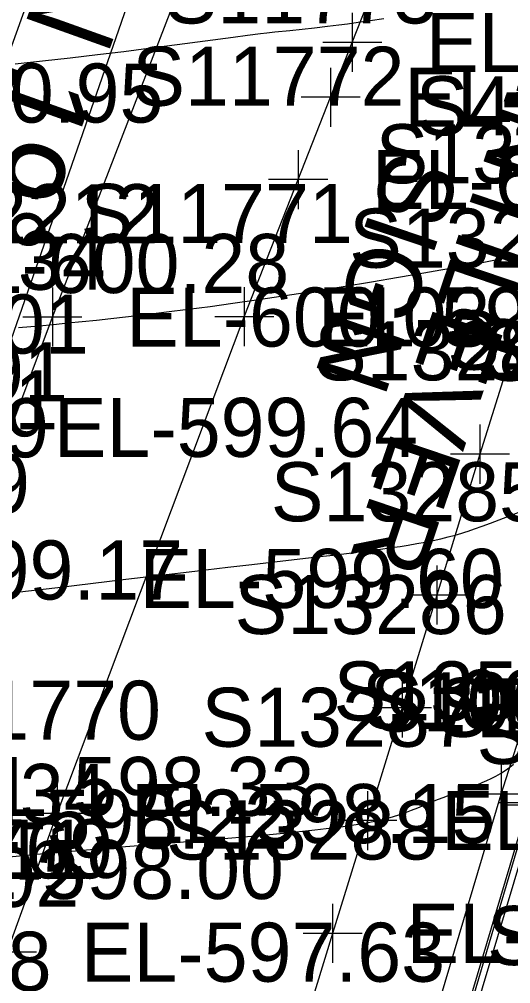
# Model space of a CAD drawing. Extents: x 1729869 to 1735532, y 648588 to 653771.
# Drawn here: x 1730424.1 to 1730457.4, y 652724.8 to 652790.1 of the extents above; entities that cross this region are included whole.
import ezdxf

# ---------------------------------------------------------------- set-up
doc = ezdxf.new("R2010")
doc.units = 0
for name, color, linetype in [('SURVEY - CENTERLINE - Preliminary', 7, 'Continuous'), ('SURVEY - CENTERLINE - Preliminary Text', 7, 'Continuous'), ('SURVEY - CONTOURS - Index with Text', 7, 'Continuous'), ('SURVEY - CONTOURS - Intermediate with optional Text', 7, 'Continuous'), ('SURVEY - DRAINAGE - Storm Sewer', 7, 'Continuous'), ('SURVEY - DRAINAGE - Storm Sewer - Points - Numbers', 7, 'Continuous'), ('SURVEY - DTM - Breaklines', 7, 'Continuous'), ('SURVEY - DTM - Breaklines - Points - Locators', 7, 'Continuous'), ('SURVEY - DTM - Breaklines - Points - Numbers', 7, 'Continuous'), ('SURVEY - ROADSIDE BARRIERS - Points - Numbers', 7, 'Continuous'), ('SURVEY - TRAFFIC CONTROL - Pavement Marking - Points - Elevations', 7, 'Continuous'), ('SURVEY - TRAFFIC CONTROL - Pavement Marking - Points - Locators', 7, 'Continuous'), ('SURVEY - TRAFFIC CONTROL - Pavement Marking - Points - Numbers', 7, 'Continuous'), ('SURVEY - TRAFFIC CONTROL - Pavement Marking with Text', 7, 'Continuous'), ('SURVEY - TRAFFIC CONTROL - Signs - Points - Elevations', 7, 'Continuous'), ('SURVEY - TRAFFIC CONTROL - Signs and Devices with Text', 7, 'Continuous'), ('SURVEY - TRANSPORTATION - Features', 7, 'Continuous'), ('SURVEY - TRANSPORTATION - Features - Points - Locators', 7, 'Continuous'), ('SURVEY - TRANSPORTATION - Features - Points - Numbers', 7, 'Continuous'), ('SURVEY - TRANSPORTATION - Roads', 7, 'Continuous'), ('SURVEY - TRANSPORTATION - Roads - Points - Elevations', 7, 'Continuous'), ('SURVEY - TRANSPORTATION - Roads - Points - Locators', 7, 'Continuous'), ('SURVEY - TRANSPORTATION - Roads - Points - Numbers', 7, 'Continuous')]:
    doc.layers.add(name, color=color, linetype=linetype)

msp = doc.modelspace()

# ---------------------------------------------------------------- linework, layer by layer
at = {"layer": 'SURVEY - CENTERLINE - Preliminary'}
msp.add_line((1730367.125, 652630.456), (1730449.207, 652859.92), dxfattribs=at)
at = {"layer": 'SURVEY - CONTOURS - Index with Text'}
msp.add_lwpolyline([(1730424.074, 652769.267), (1730425.459, 652769.388), (1730426.443, 652769.479), (1730427.415, 652769.573), (1730428.382, 652769.67), (1730429.351, 652769.772), (1730430.331, 652769.878), (1730431.328, 652769.99), (1730432.694, 652770.149), (1730434.105, 652770.319), (1730435.56, 652770.502), (1730437.059, 652770.698), (1730438.603, 652770.91), (1730440.19, 652771.137), (1730442.134, 652771.429), (1730444.106, 652771.738), (1730446.068, 652772.054), (1730447.985, 652772.372), (1730449.823, 652772.682), (1730451.545, 652772.978), (1730452.683, 652773.176), (1730453.752, 652773.364), (1730454.759, 652773.546), (1730455.711, 652773.723), (1730456.615, 652773.897), (1730457.478, 652774.071)], dxfattribs=at)
at = {"layer": 'SURVEY - CONTOURS - Intermediate with optional Text'}
for points in [[(1730423.842, 652787.131), (1730425.703, 652787.324), (1730427.575, 652787.532), (1730429.42, 652787.749), (1730431.202, 652787.968), (1730432.885, 652788.181), (1730434.827, 652788.435), (1730438.625, 652788.939), (1730439.579, 652789.063), (1730440.471, 652789.173), (1730440.899, 652789.224), (1730441.429, 652789.285), (1730442.448, 652789.396), (1730444.123, 652789.574), (1730445.014, 652789.676), (1730445.783, 652789.77), (1730446.368, 652789.846), (1730447.092, 652789.945), (1730447.908, 652790.062), (1730448.83, 652790.201)], [(1730423.274, 652751.254), (1730424.548, 652751.401), (1730426.725, 652751.658), (1730431.341, 652752.213), (1730433.691, 652752.496), (1730436.009, 652752.773), (1730438.25, 652753.037), (1730439.874, 652753.224), (1730444.289, 652753.726), (1730445.597, 652753.877), (1730446.816, 652754.022), (1730447.491, 652754.106), (1730448.137, 652754.188), (1730448.756, 652754.271), (1730449.351, 652754.355), (1730449.923, 652754.441), (1730450.476, 652754.529), (1730451.065, 652754.631), (1730451.631, 652754.737), (1730452.175, 652754.847), (1730452.694, 652754.963), (1730453.189, 652755.083), (1730453.656, 652755.208), (1730453.884, 652755.273), (1730454.106, 652755.34), (1730454.324, 652755.408), (1730454.539, 652755.479), (1730454.968, 652755.625), (1730455.498, 652755.816), (1730456.05, 652756.022), (1730457.236, 652756.472), (1730458.526, 652756.969)], [(1730422.266, 652733.296), (1730425.289, 652733.582), (1730426.691, 652733.711), (1730428.666, 652733.886), (1730431.017, 652734.09), (1730432.487, 652734.212), (1730437.72, 652734.635), (1730439.858, 652734.817), (1730442.041, 652735.018), (1730444.148, 652735.237), (1730446.062, 652735.472), (1730447.664, 652735.72), (1730447.965, 652735.777), (1730448.248, 652735.835), (1730448.514, 652735.894), (1730448.776, 652735.956), (1730449.026, 652736.02), (1730449.265, 652736.085), (1730449.781, 652736.241), (1730450.259, 652736.402), (1730450.707, 652736.569), (1730451.131, 652736.737), (1730452.236, 652737.194), (1730452.535, 652737.315), (1730452.835, 652737.433), (1730453.134, 652737.55), (1730453.435, 652737.665), (1730454.025, 652737.882), (1730454.605, 652738.094), (1730454.899, 652738.204), (1730455.195, 652738.32), (1730455.494, 652738.442), (1730455.798, 652738.574), (1730456.105, 652738.718), (1730456.414, 652738.877), (1730456.725, 652739.055), (1730457.039, 652739.256), (1730457.354, 652739.482), (1730457.614, 652739.689)]]:
    msp.add_lwpolyline(points, dxfattribs=at)
at = {"layer": 'SURVEY - DRAINAGE - Storm Sewer'}
msp.add_line((1730470.658, 652777.287), (1730443.829, 652686.59), dxfattribs=at)
at = {"layer": 'SURVEY - DTM - Breaklines'}
msp.add_lwpolyline([(1730526.762, 652924.78), (1730525.816, 652922.413), (1730522.518, 652914.459), (1730520.27, 652909.023), (1730512.149, 652888.51), (1730505.536, 652871.651), (1730496.65, 652848.401), (1730488.506, 652825.759), (1730480.552, 652802.162), (1730472.614, 652778.473), (1730471.462, 652774.953), (1730466.774, 652760.657), (1730459.184, 652736.903), (1730451.271, 652710.378), (1730444.541, 652686.351), (1730443.647, 652683.141), (1730438.618, 652664.741), (1730438.224, 652663.292), (1730437.849, 652661.806), (1730437.703, 652661.231), (1730434.552, 652649.234), (1730431.343, 652637.08), (1730428.197, 652625.141), (1730424.124, 652610.572)], dxfattribs=at)
at = {"layer": 'SURVEY - DTM - Breaklines - Points - Locators'}
msp.add_line((1730461.184, 652736.903), (1730457.184, 652736.903), dxfattribs=at)
at = {"layer": 'SURVEY - TRAFFIC CONTROL - Pavement Marking - Points - Locators'}
for p, q in [((1730446.68, 652790.581), (1730446.68, 652786.581)), ((1730448.68, 652788.581), (1730444.68, 652788.581)), ((1730445.215, 652786.863), (1730445.215, 652782.863)), ((1730447.215, 652784.863), (1730443.215, 652784.863)), ((1730443.02, 652781.287), (1730443.02, 652777.287)), ((1730445.02, 652779.287), (1730441.02, 652779.287)), ((1730426.361, 652771.975), (1730426.361, 652767.975)), ((1730439.361, 652771.994), (1730439.361, 652767.994)), ((1730428.361, 652769.975), (1730424.361, 652769.975)), ((1730441.361, 652769.994), (1730437.361, 652769.994)), ((1730426.691, 652738.343), (1730426.691, 652734.343)), ((1730428.691, 652736.343), (1730424.691, 652736.343)), ((1730425.291, 652726.952), (1730421.291, 652726.952))]:
    msp.add_line(p, q, dxfattribs=at)
at = {"layer": 'SURVEY - TRAFFIC CONTROL - Pavement Marking with Text'}
for points in [[(1730454.987, 652854.454), (1730449.188, 652839.561), (1730445.663, 652830.215), (1730442.845, 652822.739), (1730438.733, 652811.482), (1730437.37, 652807.727), (1730436.008, 652803.972), (1730435.327, 652802.094), (1730433.287, 652796.46), (1730421.466, 652762.503), (1730412.643, 652735.966), (1730408.403, 652722.644), (1730407.192, 652718.837), (1730406.586, 652716.934), (1730406.185, 652715.675)], [(1730418.622, 652713.772), (1730423.291, 652726.952), (1730426.691, 652736.343), (1730439.361, 652769.994), (1730443.02, 652779.287), (1730445.215, 652784.863), (1730446.68, 652788.581), (1730453.266, 652805.309), (1730454.007, 652807.164), (1730455.494, 652810.872), (1730465.905, 652836.83)], [(1730406.185, 652715.675), (1730406.872, 652717.551), (1730408.245, 652721.302), (1730412.367, 652732.555), (1730414.438, 652738.178), (1730426.361, 652769.975), (1730435.723, 652794.197), (1730437.19, 652797.914), (1730438.657, 652801.63), (1730439.391, 652803.488), (1730440.858, 652807.204), (1730443.071, 652812.773), (1730444.552, 652816.484), (1730446.775, 652822.049), (1730447.516, 652823.904), (1730448.257, 652825.759), (1730451.227, 652833.177)]]:
    msp.add_lwpolyline(points, dxfattribs=at)
at = {"layer": 'SURVEY - TRANSPORTATION - Features'}
for points in [[(1730427.62, 652625.314), (1730425.727, 652625.882), (1730429.117, 652638.626), (1730432.089, 652649.986), (1730435.244, 652661.984), (1730435.389, 652662.559), (1730435.764, 652664.045), (1730436.158, 652665.495), (1730441.187, 652683.891), (1730442.075, 652687.102), (1730448.86, 652711.119), (1730456.767, 652737.647), (1730464.36, 652761.409), (1730469.003, 652775.724), (1730470.146, 652779.247), (1730478.094, 652802.931), (1730486.18, 652826.496), (1730494.377, 652849.311), (1730503.254, 652872.582), (1730509.862, 652889.444), (1730517.918, 652910.002), (1730520.222, 652915.418), (1730523.56, 652923.362), (1730524.522, 652925.723)], [(1730526.309, 652924.971), (1730525.343, 652922.612), (1730522.003, 652914.674), (1730519.754, 652909.238), (1730511.611, 652888.729), (1730504.998, 652871.87), (1730496.11, 652848.617), (1730487.954, 652825.934), (1730480.004, 652802.333), (1730472.066, 652778.644), (1730470.912, 652775.126), (1730466.216, 652760.831), (1730458.625, 652737.075), (1730450.719, 652710.548), (1730443.988, 652686.519), (1730443.095, 652683.309), (1730438.066, 652664.91), (1730437.672, 652663.461), (1730437.297, 652661.975), (1730437.151, 652661.4), (1730433.976, 652649.41), (1730430.874, 652637.21), (1730427.62, 652625.314), (1730423.532, 652610.748)]]:
    msp.add_lwpolyline(points, dxfattribs=at)
at = {"layer": 'SURVEY - TRANSPORTATION - Features - Points - Locators'}
for p, q in [((1730456.767, 652739.647), (1730456.767, 652735.647)), ((1730458.767, 652737.647), (1730454.767, 652737.647)), ((1730460.625, 652737.075), (1730456.625, 652737.075))]:
    msp.add_line(p, q, dxfattribs=at)
at = {"layer": 'SURVEY - TRANSPORTATION - Roads'}
msp.add_lwpolyline([(1730477.463, 652831.212), (1730472.034, 652814.072), (1730470.846, 652810.258), (1730463.691, 652787.38), (1730459.506, 652774.037), (1730457.716, 652768.319), (1730455.341, 652760.689), (1730452.407, 652751.142), (1730450.059, 652743.503), (1730447.709, 652735.867), (1730445.357, 652728.229), (1730436.558, 652699.586), (1730430.734, 652680.478), (1730430.149, 652678.568), (1730428.979, 652674.748), (1730424.883, 652661.378), (1730420.214, 652646.096), (1730419.051, 652642.275), (1730416.146, 652632.721), (1730413.851, 652625.069), (1730412.703, 652621.243), (1730412.128, 652619.33), (1730411.555, 652617.417), (1730400.773, 652581.22)], dxfattribs=at)
at = {"layer": 'SURVEY - TRANSPORTATION - Roads - Points - Locators'}
for p, q in [((1730459.716, 652768.319), (1730455.716, 652768.319)), ((1730455.341, 652762.689), (1730455.341, 652758.689)), ((1730457.341, 652760.689), (1730453.341, 652760.689)), ((1730452.407, 652753.142), (1730452.407, 652749.142)), ((1730454.407, 652751.142), (1730450.407, 652751.142)), ((1730450.059, 652745.503), (1730450.059, 652741.503)), ((1730452.059, 652743.503), (1730448.059, 652743.503)), ((1730447.709, 652737.867), (1730447.709, 652733.867)), ((1730449.709, 652735.867), (1730445.709, 652735.867)), ((1730445.357, 652730.229), (1730445.357, 652726.229)), ((1730447.357, 652728.229), (1730443.357, 652728.229))]:
    msp.add_line(p, q, dxfattribs=at)

# ---------------------------------------------------------------- texts
at = {"layer": 'SURVEY - CENTERLINE - Preliminary Text'}
msp.add_text('N 19%%d 40\' 58" E', height=6, rotation=250.31728, dxfattribs=at).set_placement((1730426.35, 652795.03))
at = {"layer": 'SURVEY - DRAINAGE - Storm Sewer - Points - Numbers'}
msp.add_text('S427', height=4, dxfattribs=at).set_placement((1730450.986, 652782.287))
msp.add_text('S427', height=4, dxfattribs=at).set_placement((1730450.986, 652782.287))
at = {"layer": 'SURVEY - DTM - Breaklines - Points - Numbers'}
for s, p in [('S10657', (1730455.534, 652765.657)), ('S10658', (1730447.897, 652741.903)), ('S269', (1730455.82, 652726.081))]:
    msp.add_text(s, height=4, dxfattribs=at).set_placement(p)
at = {"layer": 'SURVEY - ROADSIDE BARRIERS - Points - Numbers'}
msp.add_text('S11364', height=4, dxfattribs=at).set_placement((1730455.106, 652739.699))
at = {"layer": 'SURVEY - TRAFFIC CONTROL - Pavement Marking - Points - Elevations'}
for s, p in [('EL-600.93', (1730451.68, 652786.581)), ('EL-600.95', (1730409.202, 652783.15)), ('EL-600.72', (1730450.215, 652782.863)), ('EL-600.43', (1730448.02, 652777.287)), ('EL-600.34', (1730405.29, 652771.822)), ('EL-600.28', (1730417.728, 652771.603)), ('EL-600.03', (1730431.361, 652767.975)), ('EL-599.95', (1730444.361, 652767.994)), ('EL-599.91', (1730402.723, 652764.257)), ('EL-599.81', (1730402.082, 652762.365)), ('EL-599.69', (1730401.44, 652760.473)), ('EL-599.64', (1730426.466, 652760.503)), ('EL-599.49', (1730400.156, 652756.69)), ('EL-599.17', (1730410.535, 652750.842)), ('EL-598.33', (1730419.438, 652736.178)), ('EL-598.34', (1730405.422, 652735.703)), ('EL-598.15', (1730431.691, 652734.343)), ('EL-598.22', (1730417.643, 652733.966)), ('EL-598.11', (1730404.144, 652731.918)), ('EL-598.00', (1730417.367, 652730.555)), ('EL-598.02', (1730403.505, 652730.026)), ('EL-597.63', (1730428.291, 652724.952)), ('EL-597.68', (1730401.628, 652724.336))]:
    msp.add_text(s, height=4, dxfattribs=at).set_placement(p)
at = {"layer": 'SURVEY - TRAFFIC CONTROL - Pavement Marking - Points - Numbers'}
for s, p in [('S11773', (1730433.975, 652789.863)), ('S11772', (1730431.78, 652784.287)), ('S12212', (1730415.121, 652774.975)), ('S11771', (1730428.279, 652774.994)), ('S12201', (1730410.384, 652767.503)), ('S11770', (1730415.278, 652741.343)), ('S11769', (1730412.036, 652731.952))]:
    msp.add_text(s, height=4, dxfattribs=at).set_placement(p)
at = {"layer": 'SURVEY - TRAFFIC CONTROL - Signs - Points - Elevations'}
msp.add_text('EL-599.60', height=4, dxfattribs=at).set_placement((1730432.27, 652750.271))
at = {"layer": 'SURVEY - TRAFFIC CONTROL - Signs and Devices with Text'}
for s, p in [('CANTILEVER', (1730459.926, 652793.379)), ('SIGN', (1730449.341, 652781.506))]:
    msp.add_text(s, height=5, rotation=251.30218, dxfattribs=at).set_placement(p)
at = {"layer": 'SURVEY - TRANSPORTATION - Features - Points - Numbers'}
for s, p in [('S13527', (1730453.12, 652766.409)), ('S10997', (1730454.976, 652765.831)), ('S13526', (1730445.417, 652742.647)), ('S10998', (1730447.338, 652742.075)), ('S14057', (1730452.381, 652741.538))]:
    msp.add_text(s, height=4, dxfattribs=at).set_placement(p)
at = {"layer": 'SURVEY - TRANSPORTATION - Roads - Points - Elevations'}
for s, p in [('EL-598.38', (1730455.059, 652741.503)), ('EL-598.01', (1730452.709, 652733.867)), ('EL-597.59', (1730450.357, 652726.229))]:
    msp.add_text(s, height=4, dxfattribs=at).set_placement(p)
at = {"layer": 'SURVEY - TRANSPORTATION - Roads - Points - Numbers'}
for s, p in [('S13282', (1730448.266, 652779.037)), ('S13283', (1730446.476, 652773.319)), ('S13284', (1730444.101, 652765.689)), ('S13285', (1730441.167, 652756.142)), ('S13286', (1730438.709, 652748.503)), ('S13287', (1730436.469, 652740.867)), ('S13288', (1730434.07, 652733.229))]:
    msp.add_text(s, height=4, dxfattribs=at).set_placement(p)

doc.saveas('drawing.dxf')
